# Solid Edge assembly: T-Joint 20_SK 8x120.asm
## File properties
Author: fknapp
Template: iso metric assembly.asm
Last saved by: fknapp
Revision: 8
Application: Solid Edge
Username: fknapp
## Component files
Rundzylinderscheibe_8er_Schraube_45_V3.par
SK_Schraube_8x120.par
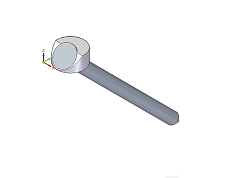
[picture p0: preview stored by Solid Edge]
